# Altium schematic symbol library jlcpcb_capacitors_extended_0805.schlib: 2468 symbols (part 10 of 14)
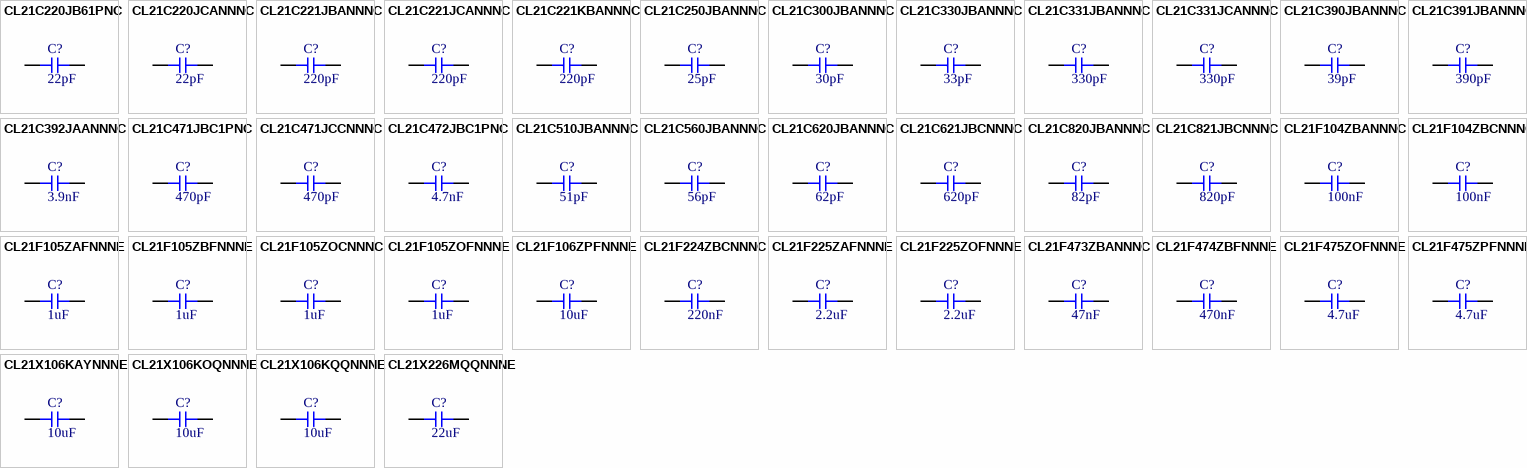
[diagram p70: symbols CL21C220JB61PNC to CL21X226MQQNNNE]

## CL21C390JBANNNC
designator C?  Capacitance: 39pF  (hidden comment: *)
Capacitor, Ceramic (MLCC), 39pF, ±5%, 50V, C0G, ±5%, SMD 0805; Manufacturer: Samsung Electro-Mechanics; Manufacturer Part Number: CL21C390JBANNNC
footprint CAP-0805 (0805 (2012M) Capacitor)
pins: 1, 2

## CL21C391JBANNNC
designator C?  Capacitance: 390pF  (hidden comment: *)
Capacitor, Ceramic (MLCC), 390pF, ±5%, 50V, C0G, ±5%, SMD 0805; Manufacturer: Samsung Electro-Mechanics; Manufacturer Part Number: CL21C391JBANNNC
footprint CAP-0805 (0805 (2012M) Capacitor)
pins: 1, 2

## CL21C392JAANNNC
designator C?  Capacitance: 3.9nF  (hidden comment: *)
Capacitor, Ceramic (MLCC), 3.9nF, ±5%, 25V, C0G, ±5%, SMD 0805; Manufacturer: Samsung Electro-Mechanics; Manufacturer Part Number: CL21C392JAANNNC
footprint CAP-0805 (0805 (2012M) Capacitor)
pins: 1, 2

## CL21C471JBC1PNC
designator C?  Capacitance: 470pF  (hidden comment: *)
Capacitor, Ceramic (MLCC), 470pF, ±5%, 50V, C0G, ±5%, SMD 0805; Manufacturer: Samsung Electro-Mechanics; Manufacturer Part Number: CL21C471JBC1PNC
footprint CAP-0805 (0805 (2012M) Capacitor)
pins: 1, 2

## CL21C471JCCNNNC
designator C?  Capacitance: 470pF  (hidden comment: *)
Capacitor, Ceramic (MLCC), 470pF, ±5%, 100V, C0G, ±5%, SMD 0805; Manufacturer: Samsung Electro-Mechanics; Manufacturer Part Number: CL21C471JCCNNNC
footprint CAP-0805 (0805 (2012M) Capacitor)
pins: 1, 2

## CL21C472JBC1PNC
designator C?  Capacitance: 4.7nF  (hidden comment: *)
Capacitor, Ceramic (MLCC), 4.7nF, ±5%, 50V, C0G, ±5%, SMD 0805; Manufacturer: Samsung Electro-Mechanics; Manufacturer Part Number: CL21C472JBC1PNC
footprint CAP-0805 (0805 (2012M) Capacitor)
pins: 1, 2

## CL21C510JBANNNC
designator C?  Capacitance: 51pF  (hidden comment: *)
Capacitor, Ceramic (MLCC), 51pF, ±5%, 50V, C0G, ±5%, SMD 0805; Manufacturer: Samsung Electro-Mechanics; Manufacturer Part Number: CL21C510JBANNNC
footprint CAP-0805 (0805 (2012M) Capacitor)
pins: 1, 2

## CL21C560JBANNNC
designator C?  Capacitance: 56pF  (hidden comment: *)
Capacitor, Ceramic (MLCC), 56pF, ±5%, 50V, C0G, ±5%, SMD 0805; Manufacturer: Samsung Electro-Mechanics; Manufacturer Part Number: CL21C560JBANNNC
footprint CAP-0805 (0805 (2012M) Capacitor)
pins: 1, 2

## CL21C620JBANNNC
designator C?  Capacitance: 62pF  (hidden comment: *)
Capacitor, Ceramic (MLCC), 62pF, ±5%, 50V, C0G, ±5%, SMD 0805; Manufacturer: Samsung Electro-Mechanics; Manufacturer Part Number: CL21C620JBANNNC
footprint CAP-0805 (0805 (2012M) Capacitor)
pins: 1, 2

## CL21C621JBCNNNC
designator C?  Capacitance: 620pF  (hidden comment: *)
Capacitor, Ceramic (MLCC), 620pF, ±5%, 50V, C0G, ±5%, SMD 0805; Manufacturer: Samsung Electro-Mechanics; Manufacturer Part Number: CL21C621JBCNNNC
footprint CAP-0805 (0805 (2012M) Capacitor)
pins: 1, 2

## CL21C820JBANNNC
designator C?  Capacitance: 82pF  (hidden comment: *)
Capacitor, Ceramic (MLCC), 82pF, ±5%, 50V, C0G, ±5%, SMD 0805; Manufacturer: Samsung Electro-Mechanics; Manufacturer Part Number: CL21C820JBANNNC
footprint CAP-0805 (0805 (2012M) Capacitor)
pins: 1, 2

## CL21C821JBCNNNC
designator C?  Capacitance: 820pF  (hidden comment: *)
Capacitor, Ceramic (MLCC), 820pF, ±5%, 50V, C0G, ±5%, SMD 0805; Manufacturer: Samsung Electro-Mechanics; Manufacturer Part Number: CL21C821JBCNNNC
footprint CAP-0805 (0805 (2012M) Capacitor)
pins: 1, 2

## CL21F104ZBANNNC
designator C?  Capacitance: 100nF  (hidden comment: *)
Capacitor, Ceramic (MLCC), 100nF, 50V, Y5V, SMD 0805; Manufacturer: Samsung Electro-Mechanics; Manufacturer Part Number: CL21F104ZBANNNC; Temperature Rating: -20%~+80%
footprint CAP-0805 (0805 (2012M) Capacitor)
pins: 1, 2

## CL21F104ZBCNNNC
designator C?  Capacitance: 100nF  (hidden comment: *)
Capacitor, Ceramic (MLCC), 100nF, 50V, Y5V, SMD 0805; Manufacturer: Samsung Electro-Mechanics; Manufacturer Part Number: CL21F104ZBCNNNC; Temperature Rating: -20%~+80%
footprint CAP-0805 (0805 (2012M) Capacitor)
pins: 1, 2

## CL21F105ZAFNNNE
designator C?  Capacitance: 1uF  (hidden comment: *)
Capacitor, Ceramic (MLCC), 1uF, 25V, Y5V, SMD 0805; Manufacturer: Samsung Electro-Mechanics; Manufacturer Part Number: CL21F105ZAFNNNE; Temperature Rating: -20%~+80%
footprint CAP-0805 (0805 (2012M) Capacitor)
pins: 1, 2

## CL21F105ZBFNNNE
designator C?  Capacitance: 1uF  (hidden comment: *)
Capacitor, Ceramic (MLCC), 1uF, 50V, Y5V, SMD 0805; Manufacturer: Samsung Electro-Mechanics; Manufacturer Part Number: CL21F105ZBFNNNE; Temperature Rating: -20%~+80%
footprint CAP-0805 (0805 (2012M) Capacitor)
pins: 1, 2

## CL21F105ZOCNNNC
designator C?  Capacitance: 1uF  (hidden comment: *)
Capacitor, Ceramic (MLCC), 1uF, 16V, Y5V, SMD 0805; Manufacturer: Samsung Electro-Mechanics; Manufacturer Part Number: CL21F105ZOCNNNC; Temperature Rating: -20%~+80%
footprint CAP-0805 (0805 (2012M) Capacitor)
pins: 1, 2

## CL21F105ZOFNNNE
designator C?  Capacitance: 1uF  (hidden comment: *)
Capacitor, Ceramic (MLCC), 1uF, 16V, Y5V, SMD 0805; Manufacturer: Samsung Electro-Mechanics; Manufacturer Part Number: CL21F105ZOFNNNE; Temperature Rating: -20%~+80%
footprint CAP-0805 (0805 (2012M) Capacitor)
pins: 1, 2

## CL21F106ZPFNNNE
designator C?  Capacitance: 10uF  (hidden comment: *)
Capacitor, Ceramic (MLCC), 10uF, 10V, Y5V, SMD 0805; Manufacturer: Samsung Electro-Mechanics; Manufacturer Part Number: CL21F106ZPFNNNE; Temperature Rating: -20%~+80%
footprint CAP-0805 (0805 (2012M) Capacitor)
pins: 1, 2

## CL21F224ZBCNNNC
designator C?  Capacitance: 220nF  (hidden comment: *)
Capacitor, Ceramic (MLCC), 220nF, 50V, Y5V, SMD 0805; Manufacturer: Samsung Electro-Mechanics; Manufacturer Part Number: CL21F224ZBCNNNC; Temperature Rating: -20%~+80%
footprint CAP-0805 (0805 (2012M) Capacitor)
pins: 1, 2

## CL21F225ZAFNNNE
designator C?  Capacitance: 2.2uF  (hidden comment: *)
Capacitor, Ceramic (MLCC), 2.2uF, 25V, Y5V, SMD 0805; Manufacturer: Samsung Electro-Mechanics; Manufacturer Part Number: CL21F225ZAFNNNE; Temperature Rating: -20%~+80%
footprint CAP-0805 (0805 (2012M) Capacitor)
pins: 1, 2

## CL21F225ZOFNNNE
designator C?  Capacitance: 2.2uF  (hidden comment: *)
Capacitor, Ceramic (MLCC), 2.2uF, 16V, Y5V, SMD 0805; Manufacturer: Samsung Electro-Mechanics; Manufacturer Part Number: CL21F225ZOFNNNE; Temperature Rating: -20%~+80%
footprint CAP-0805 (0805 (2012M) Capacitor)
pins: 1, 2

## CL21F473ZBANNNC
designator C?  Capacitance: 47nF  (hidden comment: *)
Capacitor, Ceramic (MLCC), 47nF, 50V, Y5V, SMD 0805; Manufacturer: Samsung Electro-Mechanics; Manufacturer Part Number: CL21F473ZBANNNC; Temperature Rating: -20%~+80%
footprint CAP-0805 (0805 (2012M) Capacitor)
pins: 1, 2

## CL21F474ZBFNNNE
designator C?  Capacitance: 470nF  (hidden comment: *)
Capacitor, Ceramic (MLCC), 470nF, 50V, Y5V, SMD 0805; Manufacturer: Samsung Electro-Mechanics; Manufacturer Part Number: CL21F474ZBFNNNE; Temperature Rating: -20%~+80%
footprint CAP-0805 (0805 (2012M) Capacitor)
pins: 1, 2

## CL21F475ZOFNNNE
designator C?  Capacitance: 4.7uF  (hidden comment: *)
Capacitor, Ceramic (MLCC), 4.7uF, 16V, Y5V, SMD 0805; Manufacturer: Samsung Electro-Mechanics; Manufacturer Part Number: CL21F475ZOFNNNE; Temperature Rating: -20%~+80%
footprint CAP-0805 (0805 (2012M) Capacitor)
pins: 1, 2

## CL21F475ZPFNNNE
designator C?  Capacitance: 4.7uF  (hidden comment: *)
Capacitor, Ceramic (MLCC), 4.7uF, 10V, Y5V, SMD 0805; Manufacturer: Samsung Electro-Mechanics; Manufacturer Part Number: CL21F475ZPFNNNE; Temperature Rating: -20%~+80%
footprint CAP-0805 (0805 (2012M) Capacitor)
pins: 1, 2

## CL21X106KAYNNNE
designator C?  Capacitance: 10uF  (hidden comment: *)
Capacitor, Ceramic (MLCC), 10uF, ±10%, 25V, X6S, ±10%, SMD 0805; Manufacturer: Samsung Electro-Mechanics; Manufacturer Part Number: CL21X106KAYNNNE
footprint CAP-0805 (0805 (2012M) Capacitor)
pins: 1, 2

## CL21X106KOQNNNE
designator C?  Capacitance: 10uF  (hidden comment: *)
Capacitor, Ceramic (MLCC), 10uF, ±10%, 16V, X6S, ±10%, SMD 0805; Manufacturer: Samsung Electro-Mechanics; Manufacturer Part Number: CL21X106KOQNNNE
footprint CAP-0805 (0805 (2012M) Capacitor)
pins: 1, 2

## CL21X106KQQNNNE
designator C?  Capacitance: 10uF  (hidden comment: *)
Capacitor, Ceramic (MLCC), 10uF, ±10%, 6.3V, X6S, ±10%, SMD 0805; Manufacturer: Samsung Electro-Mechanics; Manufacturer Part Number: CL21X106KQQNNNE
footprint CAP-0805 (0805 (2012M) Capacitor)
pins: 1, 2

## CL21X226MQQNNNE
designator C?  Capacitance: 22uF  (hidden comment: *)
Capacitor, Ceramic (MLCC), 22uF, ±20%, 6.3V, X6S, ±20%, SMD 0805; Manufacturer: Samsung Electro-Mechanics; Manufacturer Part Number: CL21X226MQQNNNE
footprint CAP-0805 (0805 (2012M) Capacitor)
pins: 1, 2

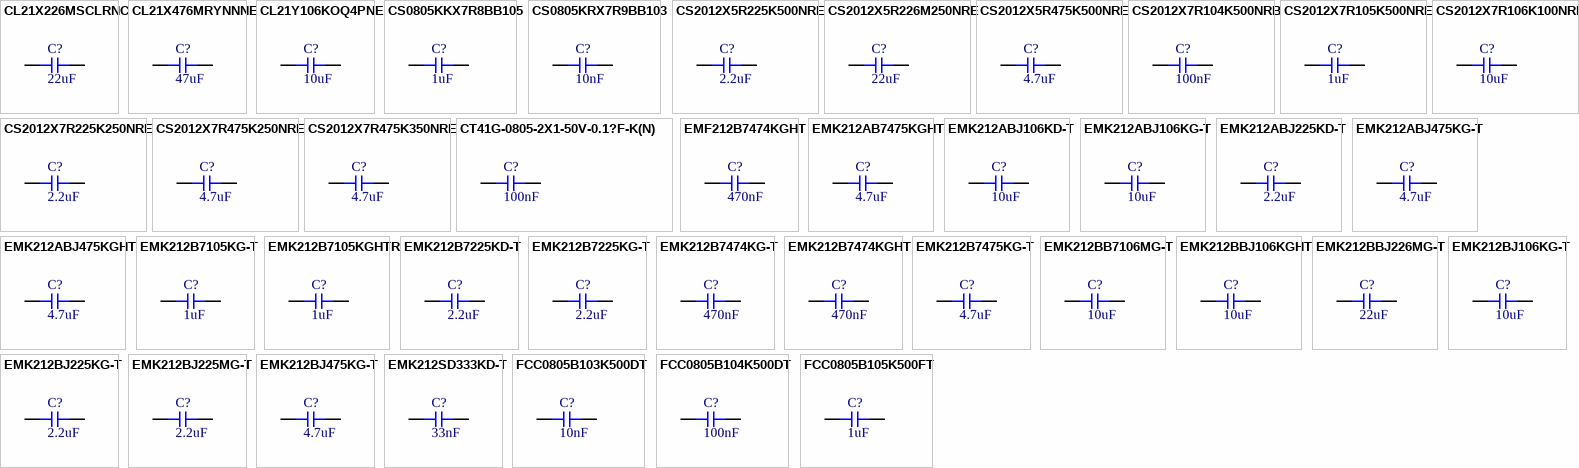
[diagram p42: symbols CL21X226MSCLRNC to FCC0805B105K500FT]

## CL21X226MSCLRNC
designator C?  Capacitance: 22uF  (hidden comment: *)
Capacitor, Ceramic (MLCC), 22uF, ±20%, 2.5V, X6S, ±20%, SMD 0805; Manufacturer: Samsung Electro-Mechanics; Manufacturer Part Number: CL21X226MSCLRNC
footprint CAP-0805 (0805 (2012M) Capacitor)
pins: 1, 2

## CL21X476MRYNNNE
designator C?  Capacitance: 47uF  (hidden comment: *)
Capacitor, Ceramic (MLCC), 47uF, ±20%, 4V, X6S, ±20%, SMD 0805; Manufacturer: Samsung Electro-Mechanics; Manufacturer Part Number: CL21X476MRYNNNE
footprint CAP-0805 (0805 (2012M) Capacitor)
pins: 1, 2

## CL21Y106KOQ4PNE
designator C?  Capacitance: 10uF  (hidden comment: *)
Capacitor, Ceramic (MLCC), 10uF, ±10%, 16V, X7S, ±10%, SMD 0805; Manufacturer: Samsung Electro-Mechanics; Manufacturer Part Number: CL21Y106KOQ4PNE
footprint CAP-0805 (0805 (2012M) Capacitor)
pins: 1, 2

## CS0805KKX7R8BB105
designator C?  Capacitance: 1uF  (hidden comment: *)
Capacitor, Ceramic (MLCC), 1uF, ±10%, 25V, X7R, ±10%, SMD 0805; Manufacturer: YAGEO; Manufacturer Part Number: CS0805KKX7R8BB105
footprint CAP-0805 (0805 (2012M) Capacitor)
pins: 1, 2

## CS0805KRX7R9BB103
designator C?  Capacitance: 10nF  (hidden comment: *)
Capacitor, Ceramic (MLCC), 10nF, ±10%, 50V, X7R, ±10%, SMD 0805; Manufacturer: YAGEO; Manufacturer Part Number: CS0805KRX7R9BB103
footprint CAP-0805 (0805 (2012M) Capacitor)
pins: 1, 2

## CS2012X5R225K500NRE
designator C?  Capacitance: 2.2uF  (hidden comment: *)
Capacitor, Ceramic (MLCC), 2.2uF, ±10%, 50V, X5R, ±10%, SMD 0805; Manufacturer: Samwha Capacitor; Manufacturer Part Number: CS2012X5R225K500NRE
footprint CAP-0805 (0805 (2012M) Capacitor)
pins: 1, 2

## CS2012X5R226M250NRE
designator C?  Capacitance: 22uF  (hidden comment: *)
Capacitor, Ceramic (MLCC), 22uF, ±20%, 25V, X5R, ±20%, SMD 0805; Manufacturer: Samwha Capacitor; Manufacturer Part Number: CS2012X5R226M250NRE
footprint CAP-0805 (0805 (2012M) Capacitor)
pins: 1, 2

## CS2012X5R475K500NRE
designator C?  Capacitance: 4.7uF  (hidden comment: *)
Capacitor, Ceramic (MLCC), 4.7uF, ±10%, 50V, X5R, ±10%, SMD 0805; Manufacturer: Samwha Capacitor; Manufacturer Part Number: CS2012X5R475K500NRE
footprint CAP-0805 (0805 (2012M) Capacitor)
pins: 1, 2

## CS2012X7R104K500NRB
designator C?  Capacitance: 100nF  (hidden comment: *)
Capacitor, Ceramic (MLCC), 100nF, ±10%, 50V, X7R, ±10%, SMD 0805; Manufacturer: Samwha Capacitor; Manufacturer Part Number: CS2012X7R104K500NRB
footprint CAP-0805 (0805 (2012M) Capacitor)
pins: 1, 2

## CS2012X7R105K500NRE
designator C?  Capacitance: 1uF  (hidden comment: *)
Capacitor, Ceramic (MLCC), 1uF, ±10%, 50V, X7R, ±10%, SMD 0805; Manufacturer: Samwha Capacitor; Manufacturer Part Number: CS2012X7R105K500NRE
footprint CAP-0805 (0805 (2012M) Capacitor)
pins: 1, 2

## CS2012X7R106K100NRE
designator C?  Capacitance: 10uF  (hidden comment: *)
Capacitor, Ceramic (MLCC), 10uF, ±10%, 10V, ±10%, SMD 0805; Manufacturer: Samwha Capacitor; Manufacturer Part Number: CS2012X7R106K100NRE
footprint CAP-0805 (0805 (2012M) Capacitor)
pins: 1, 2

## CS2012X7R225K250NRE
designator C?  Capacitance: 2.2uF  (hidden comment: *)
Capacitor, Ceramic (MLCC), 2.2uF, ±10%, 25V, ±10%, SMD 0805; Manufacturer: Samwha Capacitor; Manufacturer Part Number: CS2012X7R225K250NRE
footprint CAP-0805 (0805 (2012M) Capacitor)
pins: 1, 2

## CS2012X7R475K250NRE
designator C?  Capacitance: 4.7uF  (hidden comment: *)
Capacitor, Ceramic (MLCC), 4.7uF, ±10%, 25V, X7R, ±10%, SMD 0805; Manufacturer: Samwha Capacitor; Manufacturer Part Number: CS2012X7R475K250NRE
footprint CAP-0805 (0805 (2012M) Capacitor)
pins: 1, 2

## CS2012X7R475K350NRE
designator C?  Capacitance: 4.7uF  (hidden comment: *)
Capacitor, Ceramic (MLCC), 4.7uF, ±10%, 35V, X7R, ±10%, SMD 0805; Manufacturer: Samwha Capacitor; Manufacturer Part Number: CS2012X7R475K350NRE
footprint CAP-0805 (0805 (2012M) Capacitor)
pins: 1, 2

## CT41G-0805-2X1-50V-0.1?F-K(N)
designator C?  Capacitance: 100nF  (hidden comment: *)
Capacitor, Ceramic (MLCC), 100nF, ±10%, 50V, 2X1, ±10%, SMD 0805; Manufacturer: TORCH; Manufacturer Part Number: CT41G-0805-2X1-50V-0.1μF-K(N)
footprint CAP-0805 (0805 (2012M) Capacitor)
pins: 1, 2

## EMF212B7474KGHT
designator C?  Capacitance: 470nF  (hidden comment: *)
Capacitor, Ceramic (MLCC), 470nF, ±10%, 16V, X7R, ±10%, SMD 0805; Manufacturer: Taiyo Yuden; Manufacturer Part Number: EMF212B7474KGHT
footprint CAP-0805 (0805 (2012M) Capacitor)
pins: 1, 2

## EMK212AB7475KGHT
designator C?  Capacitance: 4.7uF  (hidden comment: *)
Capacitor, Ceramic (MLCC), 4.7uF, ±10%, 16V, X7R, ±10%, SMD 0805; Manufacturer: Taiyo Yuden; Manufacturer Part Number: EMK212AB7475KGHT
footprint CAP-0805 (0805 (2012M) Capacitor)
pins: 1, 2

## EMK212ABJ106KD-T
designator C?  Capacitance: 10uF  (hidden comment: *)
Capacitor, Ceramic (MLCC), 10uF, ±10%, 16V, X5R, ±10%, SMD 0805; Manufacturer: Taiyo Yuden; Manufacturer Part Number: EMK212ABJ106KD-T
footprint CAP-0805 (0805 (2012M) Capacitor)
pins: 1, 2

## EMK212ABJ106KG-T
designator C?  Capacitance: 10uF  (hidden comment: *)
Capacitor, Ceramic (MLCC), 10uF, ±10%, 16V, X5R, ±10%, SMD 0805; Manufacturer: Taiyo Yuden; Manufacturer Part Number: EMK212ABJ106KG-T
footprint CAP-0805 (0805 (2012M) Capacitor)
pins: 1, 2

## EMK212ABJ225KD-T
designator C?  Capacitance: 2.2uF  (hidden comment: *)
Capacitor, Ceramic (MLCC), 2.2uF, ±10%, 16V, X5R, ±10%, SMD 0805; Manufacturer: Taiyo Yuden; Manufacturer Part Number: EMK212ABJ225KD-T
footprint CAP-0805 (0805 (2012M) Capacitor)
pins: 1, 2

## EMK212ABJ475KG-T
designator C?  Capacitance: 4.7uF  (hidden comment: *)
Capacitor, Ceramic (MLCC), 4.7uF, ±10%, 16V, X5R, ±10%, SMD 0805; Manufacturer: Taiyo Yuden; Manufacturer Part Number: EMK212ABJ475KG-T
footprint CAP-0805 (0805 (2012M) Capacitor)
pins: 1, 2

## EMK212ABJ475KGHT
designator C?  Capacitance: 4.7uF  (hidden comment: *)
Capacitor, Ceramic (MLCC), 4.7uF, ±10%, 16V, ±10%, SMD 0805; Manufacturer: Taiyo Yuden; Manufacturer Part Number: EMK212ABJ475KGHT
footprint CAP-0805 (0805 (2012M) Capacitor)
pins: 1, 2

## EMK212B7105KG-T
designator C?  Capacitance: 1uF  (hidden comment: *)
Capacitor, Ceramic (MLCC), 1uF, ±10%, 16V, X7R, ±10%, SMD 0805; Manufacturer: Taiyo Yuden; Manufacturer Part Number: EMK212B7105KG-T
footprint CAP-0805 (0805 (2012M) Capacitor)
pins: 1, 2

## EMK212B7105KGHTR
designator C?  Capacitance: 1uF  (hidden comment: *)
Capacitor, Ceramic (MLCC), 1uF, ±10%, 16V, X7R, ±10%, SMD 0805; Manufacturer: Taiyo Yuden; Manufacturer Part Number: EMK212B7105KGHTR
footprint CAP-0805 (0805 (2012M) Capacitor)
pins: 1, 2

## EMK212B7225KD-T
designator C?  Capacitance: 2.2uF  (hidden comment: *)
Capacitor, Ceramic (MLCC), 2.2uF, ±10%, 16V, X7R, ±10%, SMD 0805; Manufacturer: Taiyo Yuden; Manufacturer Part Number: EMK212B7225KD-T
footprint CAP-0805 (0805 (2012M) Capacitor)
pins: 1, 2

## EMK212B7225KG-T
designator C?  Capacitance: 2.2uF  (hidden comment: *)
Capacitor, Ceramic (MLCC), 2.2uF, ±10%, 16V, X7R, ±10%, SMD 0805; Manufacturer: Taiyo Yuden; Manufacturer Part Number: EMK212B7225KG-T
footprint CAP-0805 (0805 (2012M) Capacitor)
pins: 1, 2

## EMK212B7474KG-T
designator C?  Capacitance: 470nF  (hidden comment: *)
Capacitor, Ceramic (MLCC), 470nF, ±10%, 16V, X7R, ±10%, SMD 0805; Manufacturer: Taiyo Yuden; Manufacturer Part Number: EMK212B7474KG-T
footprint CAP-0805 (0805 (2012M) Capacitor)
pins: 1, 2

## EMK212B7474KGHT
designator C?  Capacitance: 470nF  (hidden comment: *)
Capacitor, Ceramic (MLCC), 470nF, ±10%, 16V, X7R, ±10%, SMD 0805; Manufacturer: Taiyo Yuden; Manufacturer Part Number: EMK212B7474KGHT
footprint CAP-0805 (0805 (2012M) Capacitor)
pins: 1, 2

## EMK212B7475KG-T
designator C?  Capacitance: 4.7uF  (hidden comment: *)
Capacitor, Ceramic (MLCC), 4.7uF, ±10%, 16V, X7R, ±10%, SMD 0805; Manufacturer: Taiyo Yuden; Manufacturer Part Number: EMK212B7475KG-T
footprint CAP-0805 (0805 (2012M) Capacitor)
pins: 1, 2

## EMK212BB7106MG-T
designator C?  Capacitance: 10uF  (hidden comment: *)
Capacitor, Ceramic (MLCC), 10uF, ±20%, 16V, X7R, ±20%, SMD 0805; Manufacturer: Taiyo Yuden; Manufacturer Part Number: EMK212BB7106MG-T
footprint CAP-0805 (0805 (2012M) Capacitor)
pins: 1, 2

## EMK212BBJ106KGHT
designator C?  Capacitance: 10uF  (hidden comment: *)
Capacitor, Ceramic (MLCC), 10uF, ±10%, 16V, X5R, ±10%, SMD 0805; Manufacturer: Taiyo Yuden; Manufacturer Part Number: EMK212BBJ106KGHT
footprint CAP-0805 (0805 (2012M) Capacitor)
pins: 1, 2

## EMK212BBJ226MG-T
designator C?  Capacitance: 22uF  (hidden comment: *)
Capacitor, Ceramic (MLCC), 22uF, ±20%, 16V, X5R, ±20%, SMD 0805; Manufacturer: Taiyo Yuden; Manufacturer Part Number: EMK212BBJ226MG-T
footprint CAP-0805 (0805 (2012M) Capacitor)
pins: 1, 2

## EMK212BJ106KG-T
designator C?  Capacitance: 10uF  (hidden comment: *)
Capacitor, Ceramic (MLCC), 10uF, ±10%, 16V, X5R, ±10%, SMD 0805; Manufacturer: Taiyo Yuden; Manufacturer Part Number: EMK212BJ106KG-T
footprint CAP-0805 (0805 (2012M) Capacitor)
pins: 1, 2

## EMK212BJ225KG-T
designator C?  Capacitance: 2.2uF  (hidden comment: *)
Capacitor, Ceramic (MLCC), 2.2uF, ±10%, 16V, X5R, ±10%, SMD 0805; Manufacturer: Taiyo Yuden; Manufacturer Part Number: EMK212BJ225KG-T
footprint CAP-0805 (0805 (2012M) Capacitor)
pins: 1, 2

## EMK212BJ225MG-T
designator C?  Capacitance: 2.2uF  (hidden comment: *)
Capacitor, Ceramic (MLCC), 2.2uF, ±20%, 16V, X5R, ±20%, SMD 0805; Manufacturer: Taiyo Yuden; Manufacturer Part Number: EMK212BJ225MG-T
footprint CAP-0805 (0805 (2012M) Capacitor)
pins: 1, 2

## EMK212BJ475KG-T
designator C?  Capacitance: 4.7uF  (hidden comment: *)
Capacitor, Ceramic (MLCC), 4.7uF, ±10%, 16V, X5R, ±10%, SMD 0805; Manufacturer: Taiyo Yuden; Manufacturer Part Number: EMK212BJ475KG-T
footprint CAP-0805 (0805 (2012M) Capacitor)
pins: 1, 2

## EMK212SD333KD-T
designator C?  Capacitance: 33nF  (hidden comment: *)
Capacitor, Ceramic (MLCC), 33nF, ±10%, 16V, ±10%, SMD 0805; Manufacturer: Taiyo Yuden; Manufacturer Part Number: EMK212SD333KD-T
footprint CAP-0805 (0805 (2012M) Capacitor)
pins: 1, 2

## FCC0805B103K500DT
designator C?  Capacitance: 10nF  (hidden comment: *)
Capacitor, Ceramic (MLCC), 10nF, ±10%, 50V, X7R, ±10%, SMD 0805; Manufacturer: FOJAN; Manufacturer Part Number: FCC0805B103K500DT
footprint CAP-0805 (0805 (2012M) Capacitor)
pins: 1, 2

## FCC0805B104K500DT
designator C?  Capacitance: 100nF  (hidden comment: *)
Capacitor, Ceramic (MLCC), 100nF, ±10%, 50V, X7R, ±10%, SMD 0805; Manufacturer: FOJAN; Manufacturer Part Number: FCC0805B104K500DT
footprint CAP-0805 (0805 (2012M) Capacitor)
pins: 1, 2

## FCC0805B105K500FT
designator C?  Capacitance: 1uF  (hidden comment: *)
Capacitor, Ceramic (MLCC), 1uF, ±10%, 50V, X7R, ±10%, SMD 0805; Manufacturer: FOJAN; Manufacturer Part Number: FCC0805B105K500FT
footprint CAP-0805 (0805 (2012M) Capacitor)
pins: 1, 2

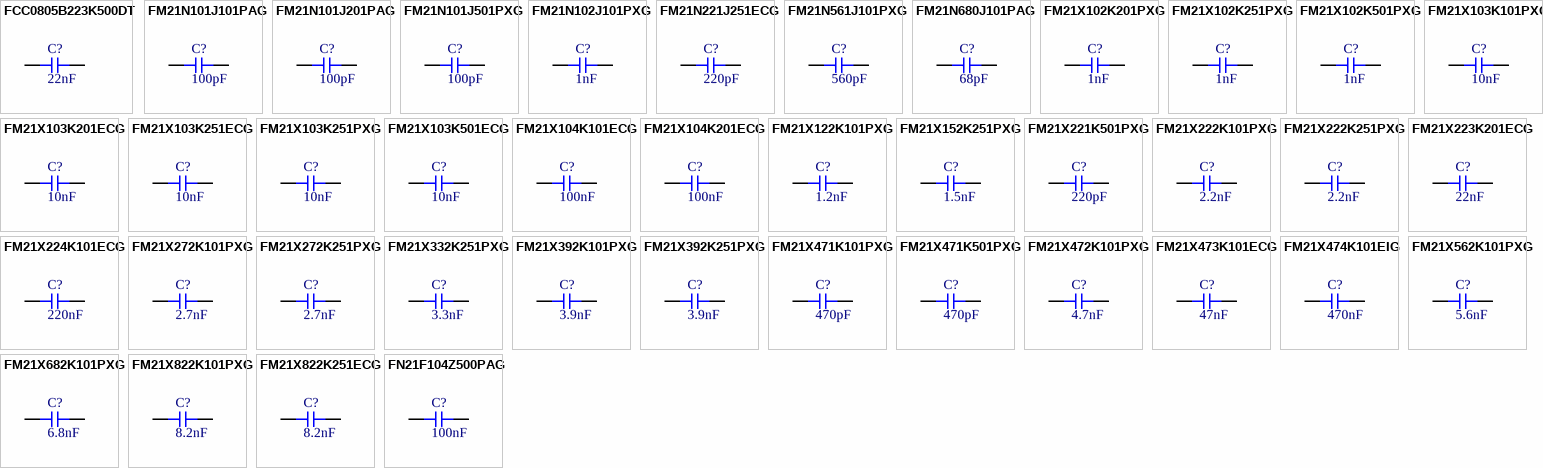
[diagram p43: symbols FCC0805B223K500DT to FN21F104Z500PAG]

## FCC0805B223K500DT
designator C?  Capacitance: 22nF  (hidden comment: *)
Capacitor, Ceramic (MLCC), 22nF, ±10%, 50V, X7R, ±10%, SMD 0805; Manufacturer: FOJAN; Manufacturer Part Number: FCC0805B223K500DT
footprint CAP-0805 (0805 (2012M) Capacitor)
pins: 1, 2

## FM21N101J101PAG
designator C?  Capacitance: 100pF  (hidden comment: *)
Capacitor, Ceramic (MLCC), 100pF, ±5%, 100V, NP0, ±5%, SMD 0805; Manufacturer: PSA(Prosperity Dielectrics); Manufacturer Part Number: FM21N101J101PAG
footprint CAP-0805 (0805 (2012M) Capacitor)
pins: 1, 2

## FM21N101J201PAG
designator C?  Capacitance: 100pF  (hidden comment: *)
Capacitor, Ceramic (MLCC), 100pF, ±5%, 200V, C0G, ±5%, SMD 0805; Manufacturer: PSA(Prosperity Dielectrics); Manufacturer Part Number: FM21N101J201PAG
footprint CAP-0805 (0805 (2012M) Capacitor)
pins: 1, 2

## FM21N101J501PXG
designator C?  Capacitance: 100pF  (hidden comment: *)
Capacitor, Ceramic (MLCC), 100pF, ±5%, 500V, C0G, ±5%, SMD 0805; Manufacturer: PSA(Prosperity Dielectrics); Manufacturer Part Number: FM21N101J501PXG
footprint CAP-0805 (0805 (2012M) Capacitor)
pins: 1, 2

## FM21N102J101PXG
designator C?  Capacitance: 1nF  (hidden comment: *)
Capacitor, Ceramic (MLCC), 1nF, ±5%, 100V, C0G, ±5%, SMD 0805; Manufacturer: PSA(Prosperity Dielectrics); Manufacturer Part Number: FM21N102J101PXG
footprint CAP-0805 (0805 (2012M) Capacitor)
pins: 1, 2

## FM21N221J251ECG
designator C?  Capacitance: 220pF  (hidden comment: *)
Capacitor, Ceramic (MLCC), 220pF, ±5%, 250V, C0G, ±5%, SMD 0805; Manufacturer: PSA(Prosperity Dielectrics); Manufacturer Part Number: FM21N221J251ECG
footprint CAP-0805 (0805 (2012M) Capacitor)
pins: 1, 2

## FM21N561J101PXG
designator C?  Capacitance: 560pF  (hidden comment: *)
Capacitor, Ceramic (MLCC), 560pF, ±5%, 100V, C0G, ±5%, SMD 0805; Manufacturer: PSA(Prosperity Dielectrics); Manufacturer Part Number: FM21N561J101PXG
footprint CAP-0805 (0805 (2012M) Capacitor)
pins: 1, 2

## FM21N680J101PAG
designator C?  Capacitance: 68pF  (hidden comment: *)
Capacitor, Ceramic (MLCC), 68pF, ±5%, 100V, C0G, ±5%, SMD 0805; Manufacturer: PSA(Prosperity Dielectrics); Manufacturer Part Number: FM21N680J101PAG
footprint CAP-0805 (0805 (2012M) Capacitor)
pins: 1, 2

## FM21X102K201PXG
designator C?  Capacitance: 1nF  (hidden comment: *)
Capacitor, Ceramic (MLCC), 1nF, ±10%, 200V, X7R, ±10%, SMD 0805; Manufacturer: PSA(Prosperity Dielectrics); Manufacturer Part Number: FM21X102K201PXG
footprint CAP-0805 (0805 (2012M) Capacitor)
pins: 1, 2

## FM21X102K251PXG
designator C?  Capacitance: 1nF  (hidden comment: *)
Capacitor, Ceramic (MLCC), 1nF, ±10%, 250V, X7R, ±10%, SMD 0805; Manufacturer: PSA(Prosperity Dielectrics); Manufacturer Part Number: FM21X102K251PXG
footprint CAP-0805 (0805 (2012M) Capacitor)
pins: 1, 2

## FM21X102K501PXG
designator C?  Capacitance: 1nF  (hidden comment: *)
Capacitor, Ceramic (MLCC), 1nF, ±10%, 500V, X7R, ±10%, SMD 0805; Manufacturer: PSA(Prosperity Dielectrics); Manufacturer Part Number: FM21X102K501PXG
footprint CAP-0805 (0805 (2012M) Capacitor)
pins: 1, 2

## FM21X103K101PXG
designator C?  Capacitance: 10nF  (hidden comment: *)
Capacitor, Ceramic (MLCC), 10nF, ±10%, 100V, X7R, ±10%, SMD 0805; Manufacturer: PSA(Prosperity Dielectrics); Manufacturer Part Number: FM21X103K101PXG
footprint CAP-0805 (0805 (2012M) Capacitor)
pins: 1, 2

## FM21X103K201ECG
designator C?  Capacitance: 10nF  (hidden comment: *)
Capacitor, Ceramic (MLCC), 10nF, ±10%, 200V, X7R, ±10%, SMD 0805; Manufacturer: PSA(Prosperity Dielectrics); Manufacturer Part Number: FM21X103K201ECG
footprint CAP-0805 (0805 (2012M) Capacitor)
pins: 1, 2

## FM21X103K251ECG
designator C?  Capacitance: 10nF  (hidden comment: *)
Capacitor, Ceramic (MLCC), 10nF, ±10%, 250V, X7R, ±10%, SMD 0805; Manufacturer: PSA(Prosperity Dielectrics); Manufacturer Part Number: FM21X103K251ECG
footprint CAP-0805 (0805 (2012M) Capacitor)
pins: 1, 2

## FM21X103K251PXG
designator C?  Capacitance: 10nF  (hidden comment: *)
Capacitor, Ceramic (MLCC), 10nF, ±10%, 250V, X7R, ±10%, SMD 0805; Manufacturer: PSA(Prosperity Dielectrics); Manufacturer Part Number: FM21X103K251PXG
footprint CAP-0805 (0805 (2012M) Capacitor)
pins: 1, 2

## FM21X103K501ECG
designator C?  Capacitance: 10nF  (hidden comment: *)
Capacitor, Ceramic (MLCC), 10nF, ±10%, 500V, X7R, ±10%, SMD 0805; Manufacturer: PSA(Prosperity Dielectrics); Manufacturer Part Number: FM21X103K501ECG
footprint CAP-0805 (0805 (2012M) Capacitor)
pins: 1, 2

## FM21X104K101ECG
designator C?  Capacitance: 100nF  (hidden comment: *)
Capacitor, Ceramic (MLCC), 100nF, ±10%, 100V, X7R, ±10%, SMD 0805; Manufacturer: PSA(Prosperity Dielectrics); Manufacturer Part Number: FM21X104K101ECG
footprint CAP-0805 (0805 (2012M) Capacitor)
pins: 1, 2

## FM21X104K201ECG
designator C?  Capacitance: 100nF  (hidden comment: *)
Capacitor, Ceramic (MLCC), 100nF, ±10%, 200V, X7R, ±10%, SMD 0805; Manufacturer: PSA(Prosperity Dielectrics); Manufacturer Part Number: FM21X104K201ECG
footprint CAP-0805 (0805 (2012M) Capacitor)
pins: 1, 2

## FM21X122K101PXG
designator C?  Capacitance: 1.2nF  (hidden comment: *)
Capacitor, Ceramic (MLCC), 1.2nF, ±10%, 100V, X7R, ±10%, SMD 0805; Manufacturer: PSA(Prosperity Dielectrics); Manufacturer Part Number: FM21X122K101PXG
footprint CAP-0805 (0805 (2012M) Capacitor)
pins: 1, 2

## FM21X152K251PXG
designator C?  Capacitance: 1.5nF  (hidden comment: *)
Capacitor, Ceramic (MLCC), 1.5nF, ±10%, 250V, X7R, ±10%, SMD 0805; Manufacturer: PSA(Prosperity Dielectrics); Manufacturer Part Number: FM21X152K251PXG
footprint CAP-0805 (0805 (2012M) Capacitor)
pins: 1, 2

## FM21X221K501PXG
designator C?  Capacitance: 220pF  (hidden comment: *)
Capacitor, Ceramic (MLCC), 220pF, ±10%, 500V, X7R, ±10%, SMD 0805; Manufacturer: PSA(Prosperity Dielectrics); Manufacturer Part Number: FM21X221K501PXG
footprint CAP-0805 (0805 (2012M) Capacitor)
pins: 1, 2

## FM21X222K101PXG
designator C?  Capacitance: 2.2nF  (hidden comment: *)
Capacitor, Ceramic (MLCC), 2.2nF, ±10%, 100V, X7R, ±10%, SMD 0805; Manufacturer: PSA(Prosperity Dielectrics); Manufacturer Part Number: FM21X222K101PXG
footprint CAP-0805 (0805 (2012M) Capacitor)
pins: 1, 2

## FM21X222K251PXG
designator C?  Capacitance: 2.2nF  (hidden comment: *)
Capacitor, Ceramic (MLCC), 2.2nF, ±10%, 250V, X7R, ±10%, SMD 0805; Manufacturer: PSA(Prosperity Dielectrics); Manufacturer Part Number: FM21X222K251PXG
footprint CAP-0805 (0805 (2012M) Capacitor)
pins: 1, 2

## FM21X223K201ECG
designator C?  Capacitance: 22nF  (hidden comment: *)
Capacitor, Ceramic (MLCC), 22nF, ±10%, 200V, X7R, ±10%, SMD 0805; Manufacturer: PSA(Prosperity Dielectrics); Manufacturer Part Number: FM21X223K201ECG
footprint CAP-0805 (0805 (2012M) Capacitor)
pins: 1, 2

## FM21X224K101ECG
designator C?  Capacitance: 220nF  (hidden comment: *)
Capacitor, Ceramic (MLCC), 220nF, ±10%, 100V, X7R, ±10%, SMD 0805; Manufacturer: PSA(Prosperity Dielectrics); Manufacturer Part Number: FM21X224K101ECG
footprint CAP-0805 (0805 (2012M) Capacitor)
pins: 1, 2

## FM21X272K101PXG
designator C?  Capacitance: 2.7nF  (hidden comment: *)
Capacitor, Ceramic (MLCC), 2.7nF, ±10%, 100V, X7R, ±10%, SMD 0805; Manufacturer: PSA(Prosperity Dielectrics); Manufacturer Part Number: FM21X272K101PXG
footprint CAP-0805 (0805 (2012M) Capacitor)
pins: 1, 2

## FM21X272K251PXG
designator C?  Capacitance: 2.7nF  (hidden comment: *)
Capacitor, Ceramic (MLCC), 2.7nF, ±10%, 250V, X7R, ±10%, SMD 0805; Manufacturer: PSA(Prosperity Dielectrics); Manufacturer Part Number: FM21X272K251PXG
footprint CAP-0805 (0805 (2012M) Capacitor)
pins: 1, 2

## FM21X332K251PXG
designator C?  Capacitance: 3.3nF  (hidden comment: *)
Capacitor, Ceramic (MLCC), 3.3nF, ±10%, 250V, X7R, ±10%, SMD 0805; Manufacturer: PSA(Prosperity Dielectrics); Manufacturer Part Number: FM21X332K251PXG
footprint CAP-0805 (0805 (2012M) Capacitor)
pins: 1, 2

## FM21X392K101PXG
designator C?  Capacitance: 3.9nF  (hidden comment: *)
Capacitor, Ceramic (MLCC), 3.9nF, ±10%, 100V, X7R, ±10%, SMD 0805; Manufacturer: PSA(Prosperity Dielectrics); Manufacturer Part Number: FM21X392K101PXG
footprint CAP-0805 (0805 (2012M) Capacitor)
pins: 1, 2

## FM21X392K251PXG
designator C?  Capacitance: 3.9nF  (hidden comment: *)
Capacitor, Ceramic (MLCC), 3.9nF, ±10%, 250V, X7R, ±10%, SMD 0805; Manufacturer: PSA(Prosperity Dielectrics); Manufacturer Part Number: FM21X392K251PXG
footprint CAP-0805 (0805 (2012M) Capacitor)
pins: 1, 2

## FM21X471K101PXG
designator C?  Capacitance: 470pF  (hidden comment: *)
Capacitor, Ceramic (MLCC), 470pF, ±10%, 100V, X7R, ±10%, SMD 0805; Manufacturer: PSA(Prosperity Dielectrics); Manufacturer Part Number: FM21X471K101PXG
footprint CAP-0805 (0805 (2012M) Capacitor)
pins: 1, 2

## FM21X471K501PXG
designator C?  Capacitance: 470pF  (hidden comment: *)
Capacitor, Ceramic (MLCC), 470pF, ±10%, 500V, X7R, ±10%, SMD 0805; Manufacturer: PSA(Prosperity Dielectrics); Manufacturer Part Number: FM21X471K501PXG
footprint CAP-0805 (0805 (2012M) Capacitor)
pins: 1, 2

## FM21X472K101PXG
designator C?  Capacitance: 4.7nF  (hidden comment: *)
Capacitor, Ceramic (MLCC), 4.7nF, ±10%, 100V, X7R, ±10%, SMD 0805; Manufacturer: PSA(Prosperity Dielectrics); Manufacturer Part Number: FM21X472K101PXG
footprint CAP-0805 (0805 (2012M) Capacitor)
pins: 1, 2

## FM21X473K101ECG
designator C?  Capacitance: 47nF  (hidden comment: *)
Capacitor, Ceramic (MLCC), 47nF, ±10%, 100V, X7R, ±10%, SMD 0805; Manufacturer: PSA(Prosperity Dielectrics); Manufacturer Part Number: FM21X473K101ECG
footprint CAP-0805 (0805 (2012M) Capacitor)
pins: 1, 2

## FM21X474K101EIG
designator C?  Capacitance: 470nF  (hidden comment: *)
Capacitor, Ceramic (MLCC), 470nF, ±10%, 100V, X7R, ±10%, SMD 0805; Manufacturer: PSA(Prosperity Dielectrics); Manufacturer Part Number: FM21X474K101EIG
footprint CAP-0805 (0805 (2012M) Capacitor)
pins: 1, 2

## FM21X562K101PXG
designator C?  Capacitance: 5.6nF  (hidden comment: *)
Capacitor, Ceramic (MLCC), 5.6nF, ±10%, 100V, X7R, ±10%, SMD 0805; Manufacturer: PSA(Prosperity Dielectrics); Manufacturer Part Number: FM21X562K101PXG
footprint CAP-0805 (0805 (2012M) Capacitor)
pins: 1, 2

## FM21X682K101PXG
designator C?  Capacitance: 6.8nF  (hidden comment: *)
Capacitor, Ceramic (MLCC), 6.8nF, ±10%, 100V, X7R, ±10%, SMD 0805; Manufacturer: PSA(Prosperity Dielectrics); Manufacturer Part Number: FM21X682K101PXG
footprint CAP-0805 (0805 (2012M) Capacitor)
pins: 1, 2

## FM21X822K101PXG
designator C?  Capacitance: 8.2nF  (hidden comment: *)
Capacitor, Ceramic (MLCC), 8.2nF, ±10%, 100V, X7R, ±10%, SMD 0805; Manufacturer: PSA(Prosperity Dielectrics); Manufacturer Part Number: FM21X822K101PXG
footprint CAP-0805 (0805 (2012M) Capacitor)
pins: 1, 2

## FM21X822K251ECG
designator C?  Capacitance: 8.2nF  (hidden comment: *)
Capacitor, Ceramic (MLCC), 8.2nF, ±10%, 250V, X7R, ±10%, SMD 0805; Manufacturer: PSA(Prosperity Dielectrics); Manufacturer Part Number: FM21X822K251ECG
footprint CAP-0805 (0805 (2012M) Capacitor)
pins: 1, 2

## FN21F104Z500PAG
designator C?  Capacitance: 100nF  (hidden comment: *)
Capacitor, Ceramic (MLCC), 100nF, 50V, Y5V, SMD 0805; Manufacturer: PSA(Prosperity Dielectrics); Manufacturer Part Number: FN21F104Z500PAG; Temperature Rating: -20%~+80%
footprint CAP-0805 (0805 (2012M) Capacitor)
pins: 1, 2

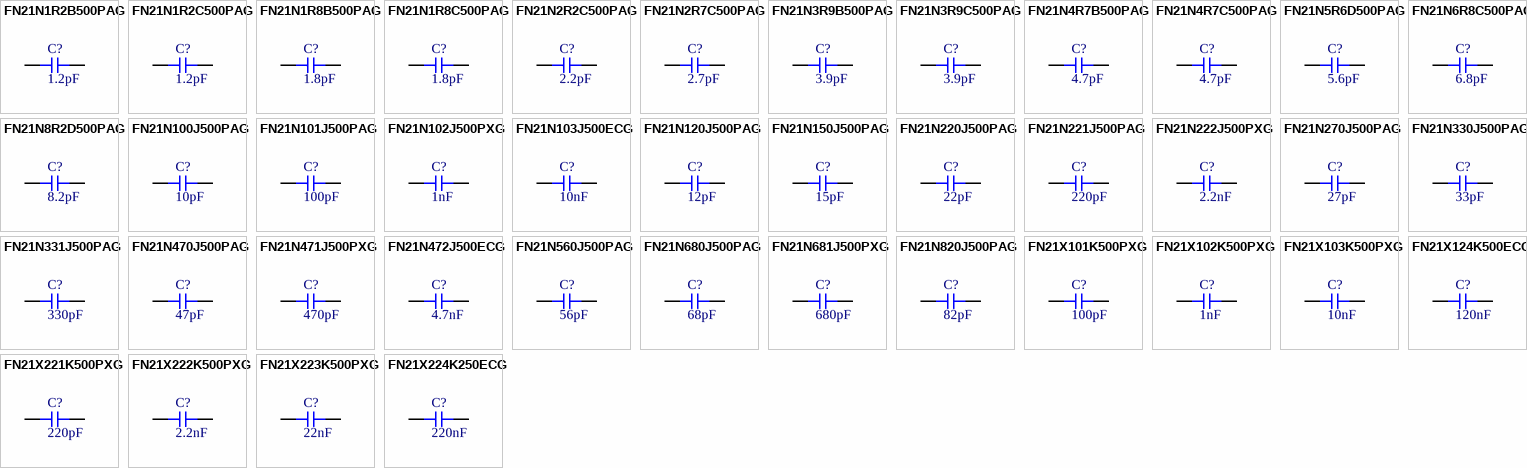
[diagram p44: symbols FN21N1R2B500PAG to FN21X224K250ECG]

## FN21N1R2B500PAG
designator C?  Capacitance: 1.2pF  (hidden comment: *)
Capacitor, Ceramic (MLCC), 1.2pF, ±0.1pF, 50V, C0G, ±0.1pF, SMD 0805; Manufacturer: PSA(Prosperity Dielectrics); Manufacturer Part Number: FN21N1R2B500PAG
footprint CAP-0805 (0805 (2012M) Capacitor)
pins: 1, 2

## FN21N1R2C500PAG
designator C?  Capacitance: 1.2pF  (hidden comment: *)
Capacitor, Ceramic (MLCC), 1.2pF, ±0.25pF, 50V, C0G, ±0.25pF, SMD 0805; Manufacturer: PSA(Prosperity Dielectrics); Manufacturer Part Number: FN21N1R2C500PAG
footprint CAP-0805 (0805 (2012M) Capacitor)
pins: 1, 2

## FN21N1R8B500PAG
designator C?  Capacitance: 1.8pF  (hidden comment: *)
Capacitor, Ceramic (MLCC), 1.8pF, ±0.1pF, 50V, C0G, ±0.1pF, SMD 0805; Manufacturer: PSA(Prosperity Dielectrics); Manufacturer Part Number: FN21N1R8B500PAG
footprint CAP-0805 (0805 (2012M) Capacitor)
pins: 1, 2

## FN21N1R8C500PAG
designator C?  Capacitance: 1.8pF  (hidden comment: *)
Capacitor, Ceramic (MLCC), 1.8pF, ±0.25pF, 50V, C0G, ±0.25pF, SMD 0805; Manufacturer: PSA(Prosperity Dielectrics); Manufacturer Part Number: FN21N1R8C500PAG
footprint CAP-0805 (0805 (2012M) Capacitor)
pins: 1, 2

## FN21N2R2C500PAG
designator C?  Capacitance: 2.2pF  (hidden comment: *)
Capacitor, Ceramic (MLCC), 2.2pF, ±0.25pF, 50V, C0G, ±0.25pF, SMD 0805; Manufacturer: PSA(Prosperity Dielectrics); Manufacturer Part Number: FN21N2R2C500PAG
footprint CAP-0805 (0805 (2012M) Capacitor)
pins: 1, 2

## FN21N2R7C500PAG
designator C?  Capacitance: 2.7pF  (hidden comment: *)
Capacitor, Ceramic (MLCC), 2.7pF, ±0.25pF, 50V, C0G, ±0.25pF, SMD 0805; Manufacturer: PSA(Prosperity Dielectrics); Manufacturer Part Number: FN21N2R7C500PAG
footprint CAP-0805 (0805 (2012M) Capacitor)
pins: 1, 2

## FN21N3R9B500PAG
designator C?  Capacitance: 3.9pF  (hidden comment: *)
Capacitor, Ceramic (MLCC), 3.9pF, ±0.1pF, 50V, C0G, ±0.1pF, SMD 0805; Manufacturer: PSA(Prosperity Dielectrics); Manufacturer Part Number: FN21N3R9B500PAG
footprint CAP-0805 (0805 (2012M) Capacitor)
pins: 1, 2

## FN21N3R9C500PAG
designator C?  Capacitance: 3.9pF  (hidden comment: *)
Capacitor, Ceramic (MLCC), 3.9pF, ±0.25pF, 50V, C0G, ±0.25pF, SMD 0805; Manufacturer: PSA(Prosperity Dielectrics); Manufacturer Part Number: FN21N3R9C500PAG
footprint CAP-0805 (0805 (2012M) Capacitor)
pins: 1, 2

## FN21N4R7B500PAG
designator C?  Capacitance: 4.7pF  (hidden comment: *)
Capacitor, Ceramic (MLCC), 4.7pF, ±0.1pF, 50V, C0G, ±0.1pF, SMD 0805; Manufacturer: PSA(Prosperity Dielectrics); Manufacturer Part Number: FN21N4R7B500PAG
footprint CAP-0805 (0805 (2012M) Capacitor)
pins: 1, 2

## FN21N4R7C500PAG
designator C?  Capacitance: 4.7pF  (hidden comment: *)
Capacitor, Ceramic (MLCC), 4.7pF, ±0.25pF, 50V, C0G, ±0.25pF, SMD 0805; Manufacturer: PSA(Prosperity Dielectrics); Manufacturer Part Number: FN21N4R7C500PAG
footprint CAP-0805 (0805 (2012M) Capacitor)
pins: 1, 2

## FN21N5R6D500PAG
designator C?  Capacitance: 5.6pF  (hidden comment: *)
Capacitor, Ceramic (MLCC), 5.6pF, ±0.5pF, 50V, C0G, ±0.5pF, SMD 0805; Manufacturer: PSA(Prosperity Dielectrics); Manufacturer Part Number: FN21N5R6D500PAG
footprint CAP-0805 (0805 (2012M) Capacitor)
pins: 1, 2

## FN21N6R8C500PAG
designator C?  Capacitance: 6.8pF  (hidden comment: *)
Capacitor, Ceramic (MLCC), 6.8pF, ±0.25pF, 50V, NP0, ±0.25pF, SMD 0805; Manufacturer: PSA(Prosperity Dielectrics); Manufacturer Part Number: FN21N6R8C500PAG
footprint CAP-0805 (0805 (2012M) Capacitor)
pins: 1, 2

## FN21N8R2D500PAG
designator C?  Capacitance: 8.2pF  (hidden comment: *)
Capacitor, Ceramic (MLCC), 8.2pF, ±0.5pF, 50V, C0G, ±0.5pF, SMD 0805; Manufacturer: PSA(Prosperity Dielectrics); Manufacturer Part Number: FN21N8R2D500PAG
footprint CAP-0805 (0805 (2012M) Capacitor)
pins: 1, 2

## FN21N100J500PAG
designator C?  Capacitance: 10pF  (hidden comment: *)
Capacitor, Ceramic (MLCC), 10pF, ±5%, 50V, C0G, ±5%, SMD 0805; Manufacturer: PSA(Prosperity Dielectrics); Manufacturer Part Number: FN21N100J500PAG
footprint CAP-0805 (0805 (2012M) Capacitor)
pins: 1, 2

## FN21N101J500PAG
designator C?  Capacitance: 100pF  (hidden comment: *)
Capacitor, Ceramic (MLCC), 100pF, ±5%, 50V, C0G, ±5%, SMD 0805; Manufacturer: PSA(Prosperity Dielectrics); Manufacturer Part Number: FN21N101J500PAG
footprint CAP-0805 (0805 (2012M) Capacitor)
pins: 1, 2

## FN21N102J500PXG
designator C?  Capacitance: 1nF  (hidden comment: *)
Capacitor, Ceramic (MLCC), 1nF, ±5%, 50V, C0G, ±5%, SMD 0805; Manufacturer: PSA(Prosperity Dielectrics); Manufacturer Part Number: FN21N102J500PXG
footprint CAP-0805 (0805 (2012M) Capacitor)
pins: 1, 2

## FN21N103J500ECG
designator C?  Capacitance: 10nF  (hidden comment: *)
Capacitor, Ceramic (MLCC), 10nF, ±5%, 50V, C0G, ±5%, SMD 0805; Manufacturer: PSA(Prosperity Dielectrics); Manufacturer Part Number: FN21N103J500ECG
footprint CAP-0805 (0805 (2012M) Capacitor)
pins: 1, 2

## FN21N120J500PAG
designator C?  Capacitance: 12pF  (hidden comment: *)
Capacitor, Ceramic (MLCC), 12pF, ±5%, 50V, C0G, ±5%, SMD 0805; Manufacturer: PSA(Prosperity Dielectrics); Manufacturer Part Number: FN21N120J500PAG
footprint CAP-0805 (0805 (2012M) Capacitor)
pins: 1, 2

## FN21N150J500PAG
designator C?  Capacitance: 15pF  (hidden comment: *)
Capacitor, Ceramic (MLCC), 15pF, ±5%, 50V, C0G, ±5%, SMD 0805; Manufacturer: PSA(Prosperity Dielectrics); Manufacturer Part Number: FN21N150J500PAG
footprint CAP-0805 (0805 (2012M) Capacitor)
pins: 1, 2

## FN21N220J500PAG
designator C?  Capacitance: 22pF  (hidden comment: *)
Capacitor, Ceramic (MLCC), 22pF, ±5%, 50V, NP0, ±5%, SMD 0805; Manufacturer: PSA(Prosperity Dielectrics); Manufacturer Part Number: FN21N220J500PAG
footprint CAP-0805 (0805 (2012M) Capacitor)
pins: 1, 2

## FN21N221J500PAG
designator C?  Capacitance: 220pF  (hidden comment: *)
Capacitor, Ceramic (MLCC), 220pF, ±5%, 50V, C0G, ±5%, SMD 0805; Manufacturer: PSA(Prosperity Dielectrics); Manufacturer Part Number: FN21N221J500PAG
footprint CAP-0805 (0805 (2012M) Capacitor)
pins: 1, 2

## FN21N222J500PXG
designator C?  Capacitance: 2.2nF  (hidden comment: *)
Capacitor, Ceramic (MLCC), 2.2nF, ±5%, 50V, NP0, ±5%, SMD 0805; Manufacturer: PSA(Prosperity Dielectrics); Manufacturer Part Number: FN21N222J500PXG
footprint CAP-0805 (0805 (2012M) Capacitor)
pins: 1, 2

## FN21N270J500PAG
designator C?  Capacitance: 27pF  (hidden comment: *)
Capacitor, Ceramic (MLCC), 27pF, ±5%, 50V, C0G, ±5%, SMD 0805; Manufacturer: PSA(Prosperity Dielectrics); Manufacturer Part Number: FN21N270J500PAG
footprint CAP-0805 (0805 (2012M) Capacitor)
pins: 1, 2

## FN21N330J500PAG
designator C?  Capacitance: 33pF  (hidden comment: *)
Capacitor, Ceramic (MLCC), 33pF, ±5%, 50V, C0G, ±5%, SMD 0805; Manufacturer: PSA(Prosperity Dielectrics); Manufacturer Part Number: FN21N330J500PAG
footprint CAP-0805 (0805 (2012M) Capacitor)
pins: 1, 2

## FN21N331J500PAG
designator C?  Capacitance: 330pF  (hidden comment: *)
Capacitor, Ceramic (MLCC), 330pF, ±5%, 50V, C0G, ±5%, SMD 0805; Manufacturer: PSA(Prosperity Dielectrics); Manufacturer Part Number: FN21N331J500PAG
footprint CAP-0805 (0805 (2012M) Capacitor)
pins: 1, 2

## FN21N470J500PAG
designator C?  Capacitance: 47pF  (hidden comment: *)
Capacitor, Ceramic (MLCC), 47pF, ±5%, 50V, C0G, ±5%, SMD 0805; Manufacturer: PSA(Prosperity Dielectrics); Manufacturer Part Number: FN21N470J500PAG
footprint CAP-0805 (0805 (2012M) Capacitor)
pins: 1, 2

## FN21N471J500PXG
designator C?  Capacitance: 470pF  (hidden comment: *)
Capacitor, Ceramic (MLCC), 470pF, ±5%, 50V, C0G, ±5%, SMD 0805; Manufacturer: PSA(Prosperity Dielectrics); Manufacturer Part Number: FN21N471J500PXG
footprint CAP-0805 (0805 (2012M) Capacitor)
pins: 1, 2

## FN21N472J500ECG
designator C?  Capacitance: 4.7nF  (hidden comment: *)
Capacitor, Ceramic (MLCC), 4.7nF, ±5%, 50V, NP0, ±5%, SMD 0805; Manufacturer: PSA(Prosperity Dielectrics); Manufacturer Part Number: FN21N472J500ECG
footprint CAP-0805 (0805 (2012M) Capacitor)
pins: 1, 2

## FN21N560J500PAG
designator C?  Capacitance: 56pF  (hidden comment: *)
Capacitor, Ceramic (MLCC), 56pF, ±5%, 50V, C0G, ±5%, SMD 0805; Manufacturer: PSA(Prosperity Dielectrics); Manufacturer Part Number: FN21N560J500PAG
footprint CAP-0805 (0805 (2012M) Capacitor)
pins: 1, 2

## FN21N680J500PAG
designator C?  Capacitance: 68pF  (hidden comment: *)
Capacitor, Ceramic (MLCC), 68pF, ±5%, 50V, C0G, ±5%, SMD 0805; Manufacturer: PSA(Prosperity Dielectrics); Manufacturer Part Number: FN21N680J500PAG
footprint CAP-0805 (0805 (2012M) Capacitor)
pins: 1, 2

## FN21N681J500PXG
designator C?  Capacitance: 680pF  (hidden comment: *)
Capacitor, Ceramic (MLCC), 680pF, ±5%, 50V, C0G, ±5%, SMD 0805; Manufacturer: PSA(Prosperity Dielectrics); Manufacturer Part Number: FN21N681J500PXG
footprint CAP-0805 (0805 (2012M) Capacitor)
pins: 1, 2

## FN21N820J500PAG
designator C?  Capacitance: 82pF  (hidden comment: *)
Capacitor, Ceramic (MLCC), 82pF, ±5%, 50V, C0G, ±5%, SMD 0805; Manufacturer: PSA(Prosperity Dielectrics); Manufacturer Part Number: FN21N820J500PAG
footprint CAP-0805 (0805 (2012M) Capacitor)
pins: 1, 2

## FN21X101K500PXG
designator C?  Capacitance: 100pF  (hidden comment: *)
Capacitor, Ceramic (MLCC), 100pF, ±10%, 50V, X7R, ±10%, SMD 0805; Manufacturer: PSA(Prosperity Dielectrics); Manufacturer Part Number: FN21X101K500PXG
footprint CAP-0805 (0805 (2012M) Capacitor)
pins: 1, 2

## FN21X102K500PXG
designator C?  Capacitance: 1nF  (hidden comment: *)
Capacitor, Ceramic (MLCC), 1nF, ±10%, 50V, X7R, ±10%, SMD 0805; Manufacturer: PSA(Prosperity Dielectrics); Manufacturer Part Number: FN21X102K500PXG
footprint CAP-0805 (0805 (2012M) Capacitor)
pins: 1, 2

## FN21X103K500PXG
designator C?  Capacitance: 10nF  (hidden comment: *)
Capacitor, Ceramic (MLCC), 10nF, ±10%, 50V, X7R, ±10%, SMD 0805; Manufacturer: PSA(Prosperity Dielectrics); Manufacturer Part Number: FN21X103K500PXG
footprint CAP-0805 (0805 (2012M) Capacitor)
pins: 1, 2

## FN21X124K500ECG
designator C?  Capacitance: 120nF  (hidden comment: *)
Capacitor, Ceramic (MLCC), 120nF, ±10%, 50V, X7R, ±10%, SMD 0805; Manufacturer: PSA(Prosperity Dielectrics); Manufacturer Part Number: FN21X124K500ECG
footprint CAP-0805 (0805 (2012M) Capacitor)
pins: 1, 2

## FN21X221K500PXG
designator C?  Capacitance: 220pF  (hidden comment: *)
Capacitor, Ceramic (MLCC), 220pF, ±10%, 50V, X7R, ±10%, SMD 0805; Manufacturer: PSA(Prosperity Dielectrics); Manufacturer Part Number: FN21X221K500PXG
footprint CAP-0805 (0805 (2012M) Capacitor)
pins: 1, 2

## FN21X222K500PXG
designator C?  Capacitance: 2.2nF  (hidden comment: *)
Capacitor, Ceramic (MLCC), 2.2nF, ±10%, 50V, X7R, ±10%, SMD 0805; Manufacturer: PSA(Prosperity Dielectrics); Manufacturer Part Number: FN21X222K500PXG
footprint CAP-0805 (0805 (2012M) Capacitor)
pins: 1, 2

## FN21X223K500PXG
designator C?  Capacitance: 22nF  (hidden comment: *)
Capacitor, Ceramic (MLCC), 22nF, ±10%, 50V, X7R, ±10%, SMD 0805; Manufacturer: PSA(Prosperity Dielectrics); Manufacturer Part Number: FN21X223K500PXG
footprint CAP-0805 (0805 (2012M) Capacitor)
pins: 1, 2

## FN21X224K250ECG
designator C?  Capacitance: 220nF  (hidden comment: *)
Capacitor, Ceramic (MLCC), 220nF, ±10%, 25V, X7R, ±10%, SMD 0805; Manufacturer: PSA(Prosperity Dielectrics); Manufacturer Part Number: FN21X224K250ECG
footprint CAP-0805 (0805 (2012M) Capacitor)
pins: 1, 2

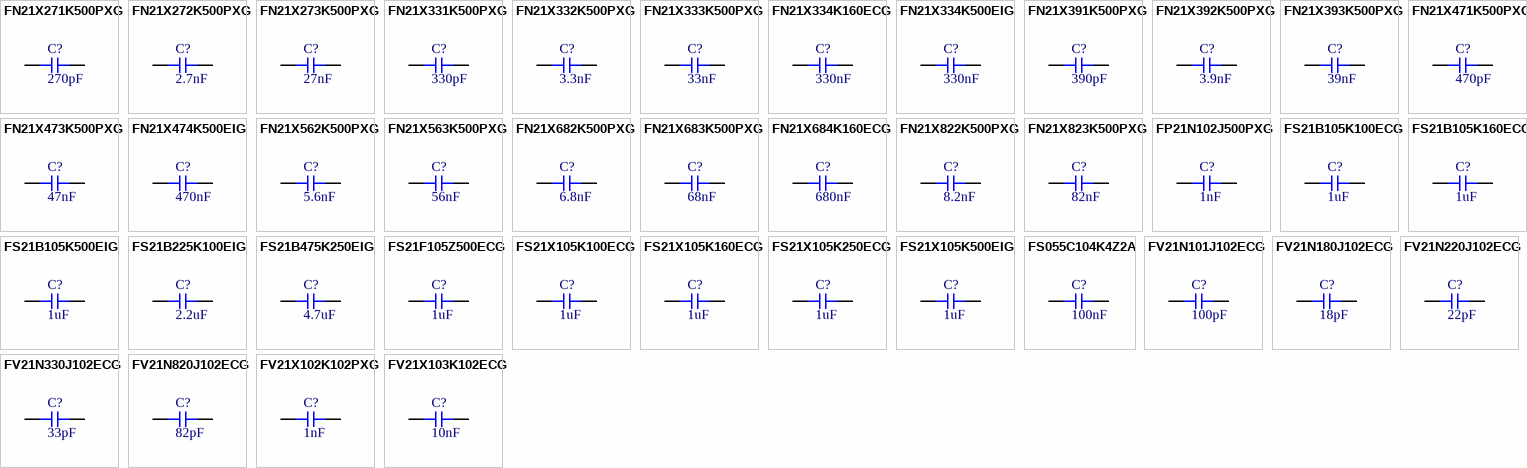
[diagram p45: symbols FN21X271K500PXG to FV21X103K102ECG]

## FN21X271K500PXG
designator C?  Capacitance: 270pF  (hidden comment: *)
Capacitor, Ceramic (MLCC), 270pF, ±10%, 50V, X7R, ±10%, SMD 0805; Manufacturer: PSA(Prosperity Dielectrics); Manufacturer Part Number: FN21X271K500PXG
footprint CAP-0805 (0805 (2012M) Capacitor)
pins: 1, 2

## FN21X272K500PXG
designator C?  Capacitance: 2.7nF  (hidden comment: *)
Capacitor, Ceramic (MLCC), 2.7nF, ±10%, 50V, X7R, ±10%, SMD 0805; Manufacturer: PSA(Prosperity Dielectrics); Manufacturer Part Number: FN21X272K500PXG
footprint CAP-0805 (0805 (2012M) Capacitor)
pins: 1, 2

## FN21X273K500PXG
designator C?  Capacitance: 27nF  (hidden comment: *)
Capacitor, Ceramic (MLCC), 27nF, ±10%, 50V, X7R, ±10%, SMD 0805; Manufacturer: PSA(Prosperity Dielectrics); Manufacturer Part Number: FN21X273K500PXG
footprint CAP-0805 (0805 (2012M) Capacitor)
pins: 1, 2

## FN21X331K500PXG
designator C?  Capacitance: 330pF  (hidden comment: *)
Capacitor, Ceramic (MLCC), 330pF, ±10%, 50V, X7R, ±10%, SMD 0805; Manufacturer: PSA(Prosperity Dielectrics); Manufacturer Part Number: FN21X331K500PXG
footprint CAP-0805 (0805 (2012M) Capacitor)
pins: 1, 2

## FN21X332K500PXG
designator C?  Capacitance: 3.3nF  (hidden comment: *)
Capacitor, Ceramic (MLCC), 3.3nF, ±10%, 50V, X7R, ±10%, SMD 0805; Manufacturer: PSA(Prosperity Dielectrics); Manufacturer Part Number: FN21X332K500PXG
footprint CAP-0805 (0805 (2012M) Capacitor)
pins: 1, 2

## FN21X333K500PXG
designator C?  Capacitance: 33nF  (hidden comment: *)
Capacitor, Ceramic (MLCC), 33nF, ±10%, 50V, X7R, ±10%, SMD 0805; Manufacturer: PSA(Prosperity Dielectrics); Manufacturer Part Number: FN21X333K500PXG
footprint CAP-0805 (0805 (2012M) Capacitor)
pins: 1, 2

## FN21X334K160ECG
designator C?  Capacitance: 330nF  (hidden comment: *)
Capacitor, Ceramic (MLCC), 330nF, ±10%, 16V, X7R, ±10%, SMD 0805; Manufacturer: PSA(Prosperity Dielectrics); Manufacturer Part Number: FN21X334K160ECG
footprint CAP-0805 (0805 (2012M) Capacitor)
pins: 1, 2

## FN21X334K500EIG
designator C?  Capacitance: 330nF  (hidden comment: *)
Capacitor, Ceramic (MLCC), 330nF, ±10%, 50V, X7R, ±10%, SMD 0805; Manufacturer: PSA(Prosperity Dielectrics); Manufacturer Part Number: FN21X334K500EIG
footprint CAP-0805 (0805 (2012M) Capacitor)
pins: 1, 2

## FN21X391K500PXG
designator C?  Capacitance: 390pF  (hidden comment: *)
Capacitor, Ceramic (MLCC), 390pF, ±10%, 50V, X7R, ±10%, SMD 0805; Manufacturer: PSA(Prosperity Dielectrics); Manufacturer Part Number: FN21X391K500PXG
footprint CAP-0805 (0805 (2012M) Capacitor)
pins: 1, 2

## FN21X392K500PXG
designator C?  Capacitance: 3.9nF  (hidden comment: *)
Capacitor, Ceramic (MLCC), 3.9nF, ±10%, 50V, X7R, ±10%, SMD 0805; Manufacturer: PSA(Prosperity Dielectrics); Manufacturer Part Number: FN21X392K500PXG
footprint CAP-0805 (0805 (2012M) Capacitor)
pins: 1, 2

## FN21X393K500PXG
designator C?  Capacitance: 39nF  (hidden comment: *)
Capacitor, Ceramic (MLCC), 39nF, ±10%, 50V, X7R, ±10%, SMD 0805; Manufacturer: PSA(Prosperity Dielectrics); Manufacturer Part Number: FN21X393K500PXG
footprint CAP-0805 (0805 (2012M) Capacitor)
pins: 1, 2

## FN21X471K500PXG
designator C?  Capacitance: 470pF  (hidden comment: *)
Capacitor, Ceramic (MLCC), 470pF, ±10%, 50V, X7R, ±10%, SMD 0805; Manufacturer: PSA(Prosperity Dielectrics); Manufacturer Part Number: FN21X471K500PXG
footprint CAP-0805 (0805 (2012M) Capacitor)
pins: 1, 2

## FN21X473K500PXG
designator C?  Capacitance: 47nF  (hidden comment: *)
Capacitor, Ceramic (MLCC), 47nF, ±10%, 50V, X7R, ±10%, SMD 0805; Manufacturer: PSA(Prosperity Dielectrics); Manufacturer Part Number: FN21X473K500PXG
footprint CAP-0805 (0805 (2012M) Capacitor)
pins: 1, 2

## FN21X474K500EIG
designator C?  Capacitance: 470nF  (hidden comment: *)
Capacitor, Ceramic (MLCC), 470nF, ±10%, 50V, X7R, ±10%, SMD 0805; Manufacturer: PSA(Prosperity Dielectrics); Manufacturer Part Number: FN21X474K500EIG
footprint CAP-0805 (0805 (2012M) Capacitor)
pins: 1, 2

## FN21X562K500PXG
designator C?  Capacitance: 5.6nF  (hidden comment: *)
Capacitor, Ceramic (MLCC), 5.6nF, ±10%, 50V, X7R, ±10%, SMD 0805; Manufacturer: PSA(Prosperity Dielectrics); Manufacturer Part Number: FN21X562K500PXG
footprint CAP-0805 (0805 (2012M) Capacitor)
pins: 1, 2

## FN21X563K500PXG
designator C?  Capacitance: 56nF  (hidden comment: *)
Capacitor, Ceramic (MLCC), 56nF, ±10%, 50V, X7R, ±10%, SMD 0805; Manufacturer: PSA(Prosperity Dielectrics); Manufacturer Part Number: FN21X563K500PXG
footprint CAP-0805 (0805 (2012M) Capacitor)
pins: 1, 2

## FN21X682K500PXG
designator C?  Capacitance: 6.8nF  (hidden comment: *)
Capacitor, Ceramic (MLCC), 6.8nF, ±10%, 50V, X7R, ±10%, SMD 0805; Manufacturer: PSA(Prosperity Dielectrics); Manufacturer Part Number: FN21X682K500PXG
footprint CAP-0805 (0805 (2012M) Capacitor)
pins: 1, 2

## FN21X683K500PXG
designator C?  Capacitance: 68nF  (hidden comment: *)
Capacitor, Ceramic (MLCC), 68nF, ±10%, 50V, X7R, ±10%, SMD 0805; Manufacturer: PSA(Prosperity Dielectrics); Manufacturer Part Number: FN21X683K500PXG
footprint CAP-0805 (0805 (2012M) Capacitor)
pins: 1, 2

## FN21X684K160ECG
designator C?  Capacitance: 680nF  (hidden comment: *)
Capacitor, Ceramic (MLCC), 680nF, ±10%, 16V, X7R, ±10%, SMD 0805; Manufacturer: PSA(Prosperity Dielectrics); Manufacturer Part Number: FN21X684K160ECG
footprint CAP-0805 (0805 (2012M) Capacitor)
pins: 1, 2

## FN21X822K500PXG
designator C?  Capacitance: 8.2nF  (hidden comment: *)
Capacitor, Ceramic (MLCC), 8.2nF, ±10%, 50V, X7R, ±10%, SMD 0805; Manufacturer: PSA(Prosperity Dielectrics); Manufacturer Part Number: FN21X822K500PXG
footprint CAP-0805 (0805 (2012M) Capacitor)
pins: 1, 2

## FN21X823K500PXG
designator C?  Capacitance: 82nF  (hidden comment: *)
Capacitor, Ceramic (MLCC), 82nF, ±10%, 50V, X7R, ±10%, SMD 0805; Manufacturer: PSA(Prosperity Dielectrics); Manufacturer Part Number: FN21X823K500PXG
footprint CAP-0805 (0805 (2012M) Capacitor)
pins: 1, 2

## FP21N102J500PXG
designator C?  Capacitance: 1nF  (hidden comment: *)
Capacitor, Ceramic (MLCC), 1nF, ±5%, 50V, C0G, ±5%, SMD 0805; Manufacturer: PSA(Prosperity Dielectrics); Manufacturer Part Number: FP21N102J500PXG
footprint CAP-0805 (0805 (2012M) Capacitor)
pins: 1, 2

## FS21B105K100ECG
designator C?  Capacitance: 1uF  (hidden comment: *)
Capacitor, Ceramic (MLCC), 1uF, ±10%, 10V, X5R, ±10%, SMD 0805; Manufacturer: PSA(Prosperity Dielectrics); Manufacturer Part Number: FS21B105K100ECG
footprint CAP-0805 (0805 (2012M) Capacitor)
pins: 1, 2

## FS21B105K160ECG
designator C?  Capacitance: 1uF  (hidden comment: *)
Capacitor, Ceramic (MLCC), 1uF, ±10%, 16V, X5R, ±10%, SMD 0805; Manufacturer: PSA(Prosperity Dielectrics); Manufacturer Part Number: FS21B105K160ECG
footprint CAP-0805 (0805 (2012M) Capacitor)
pins: 1, 2

## FS21B105K500EIG
designator C?  Capacitance: 1uF  (hidden comment: *)
Capacitor, Ceramic (MLCC), 1uF, ±10%, 50V, X5R, ±10%, SMD 0805; Manufacturer: PSA(Prosperity Dielectrics); Manufacturer Part Number: FS21B105K500EIG
footprint CAP-0805 (0805 (2012M) Capacitor)
pins: 1, 2

## FS21B225K100EIG
designator C?  Capacitance: 2.2uF  (hidden comment: *)
Capacitor, Ceramic (MLCC), 2.2uF, ±10%, 10V, X5R, ±10%, SMD 0805; Manufacturer: PSA(Prosperity Dielectrics); Manufacturer Part Number: FS21B225K100EIG
footprint CAP-0805 (0805 (2012M) Capacitor)
pins: 1, 2

## FS21B475K250EIG
designator C?  Capacitance: 4.7uF  (hidden comment: *)
Capacitor, Ceramic (MLCC), 4.7uF, ±10%, 25V, X5R, ±10%, SMD 0805; Manufacturer: PSA(Prosperity Dielectrics); Manufacturer Part Number: FS21B475K250EIG
footprint CAP-0805 (0805 (2012M) Capacitor)
pins: 1, 2

## FS21F105Z500ECG
designator C?  Capacitance: 1uF  (hidden comment: *)
Capacitor, Ceramic (MLCC), 1uF, 50V, Y5V, SMD 0805; Manufacturer: PSA(Prosperity Dielectrics); Manufacturer Part Number: FS21F105Z500ECG; Temperature Rating: -20%~+80%
footprint CAP-0805 (0805 (2012M) Capacitor)
pins: 1, 2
